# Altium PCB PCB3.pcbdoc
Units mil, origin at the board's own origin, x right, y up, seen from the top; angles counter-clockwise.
Board outline 4316.11 x 3910.52 mil, 4 copper layers (Top Layer, Inner1, Inner2, Bottom Layer), stack 5.512 mil thick; 63 components, 48 nets, 264 pads, 108 vias.
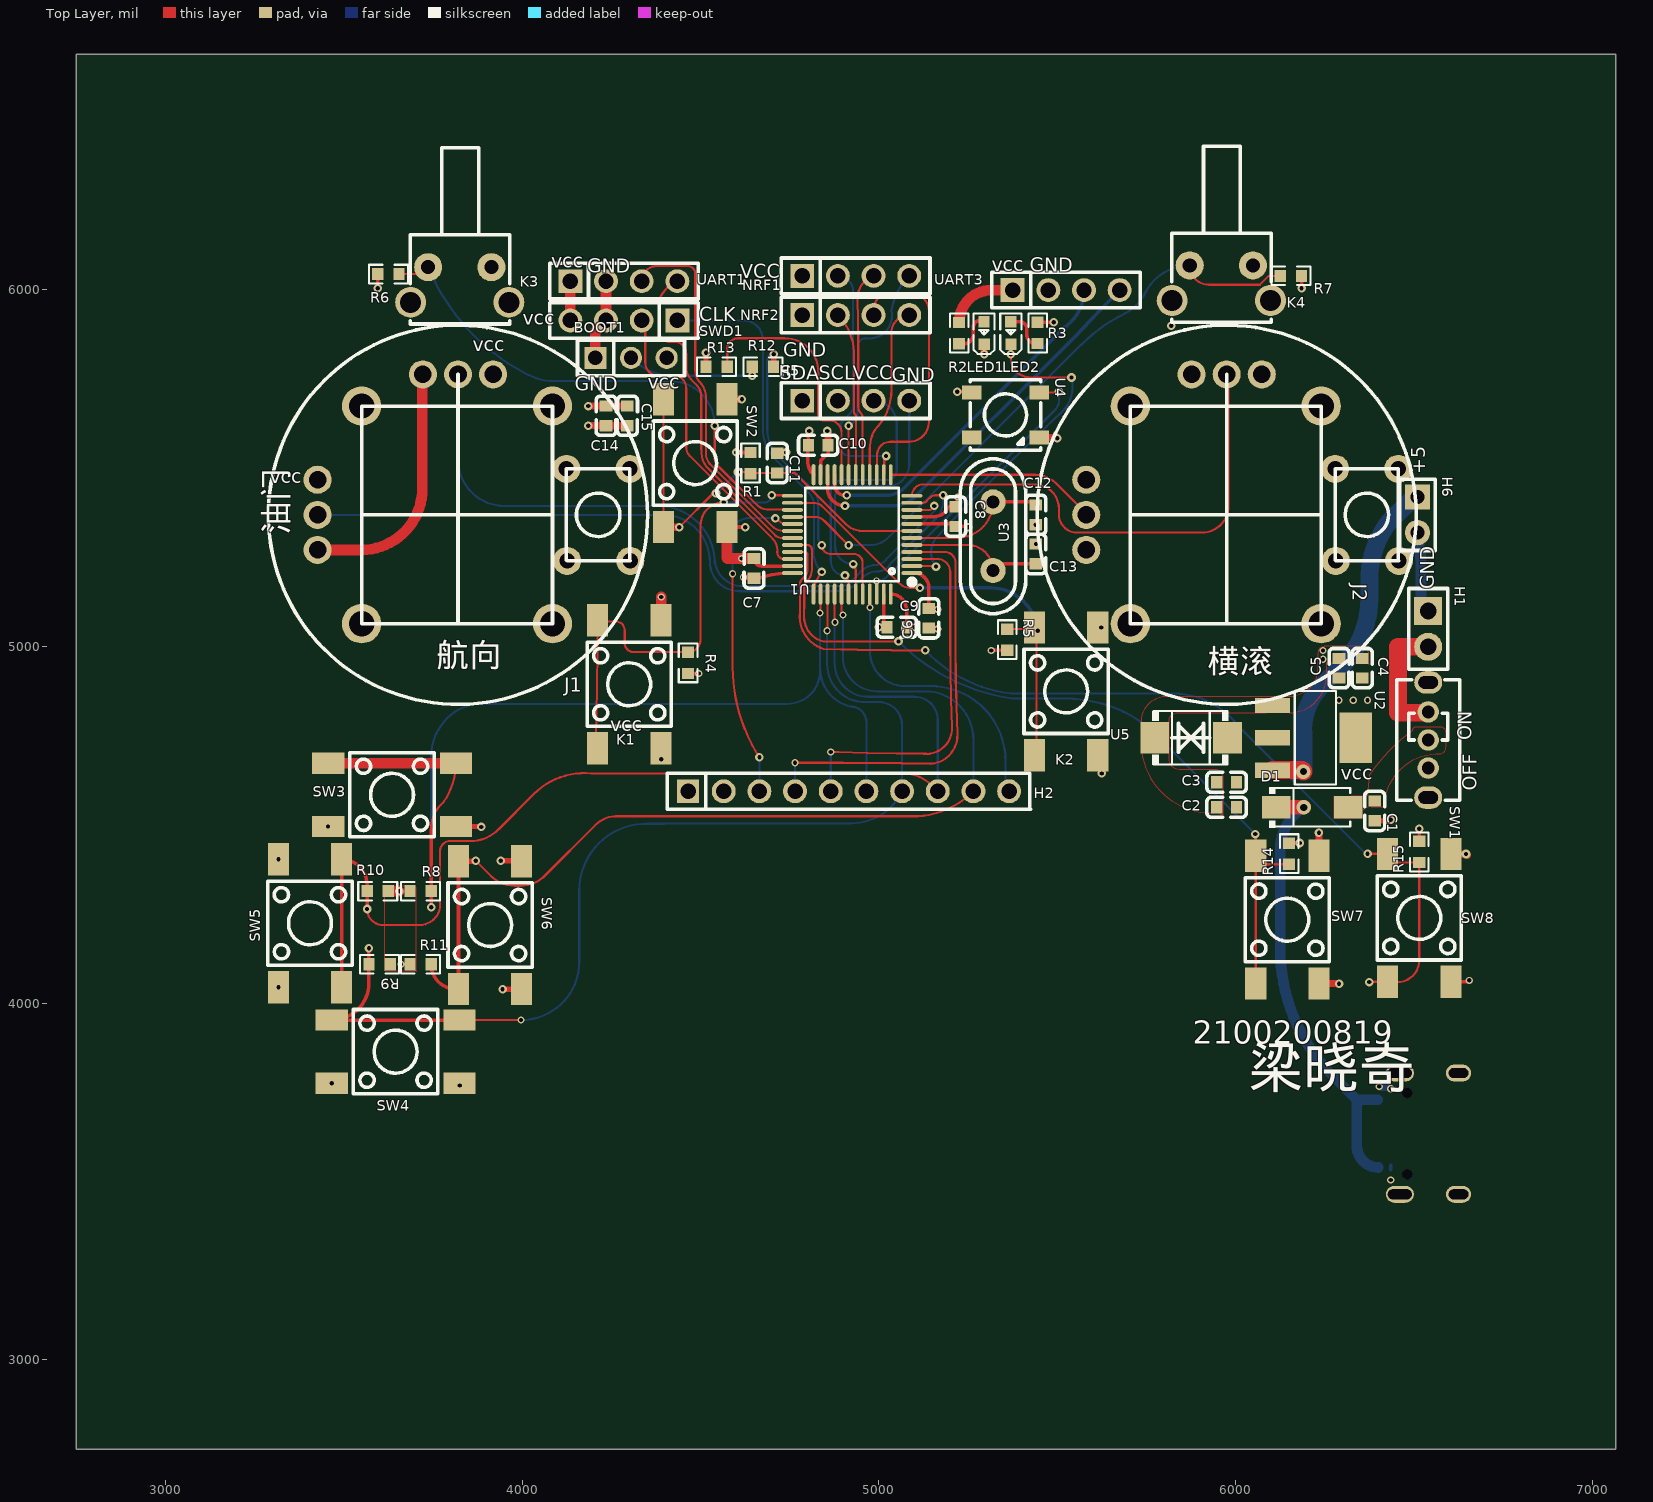
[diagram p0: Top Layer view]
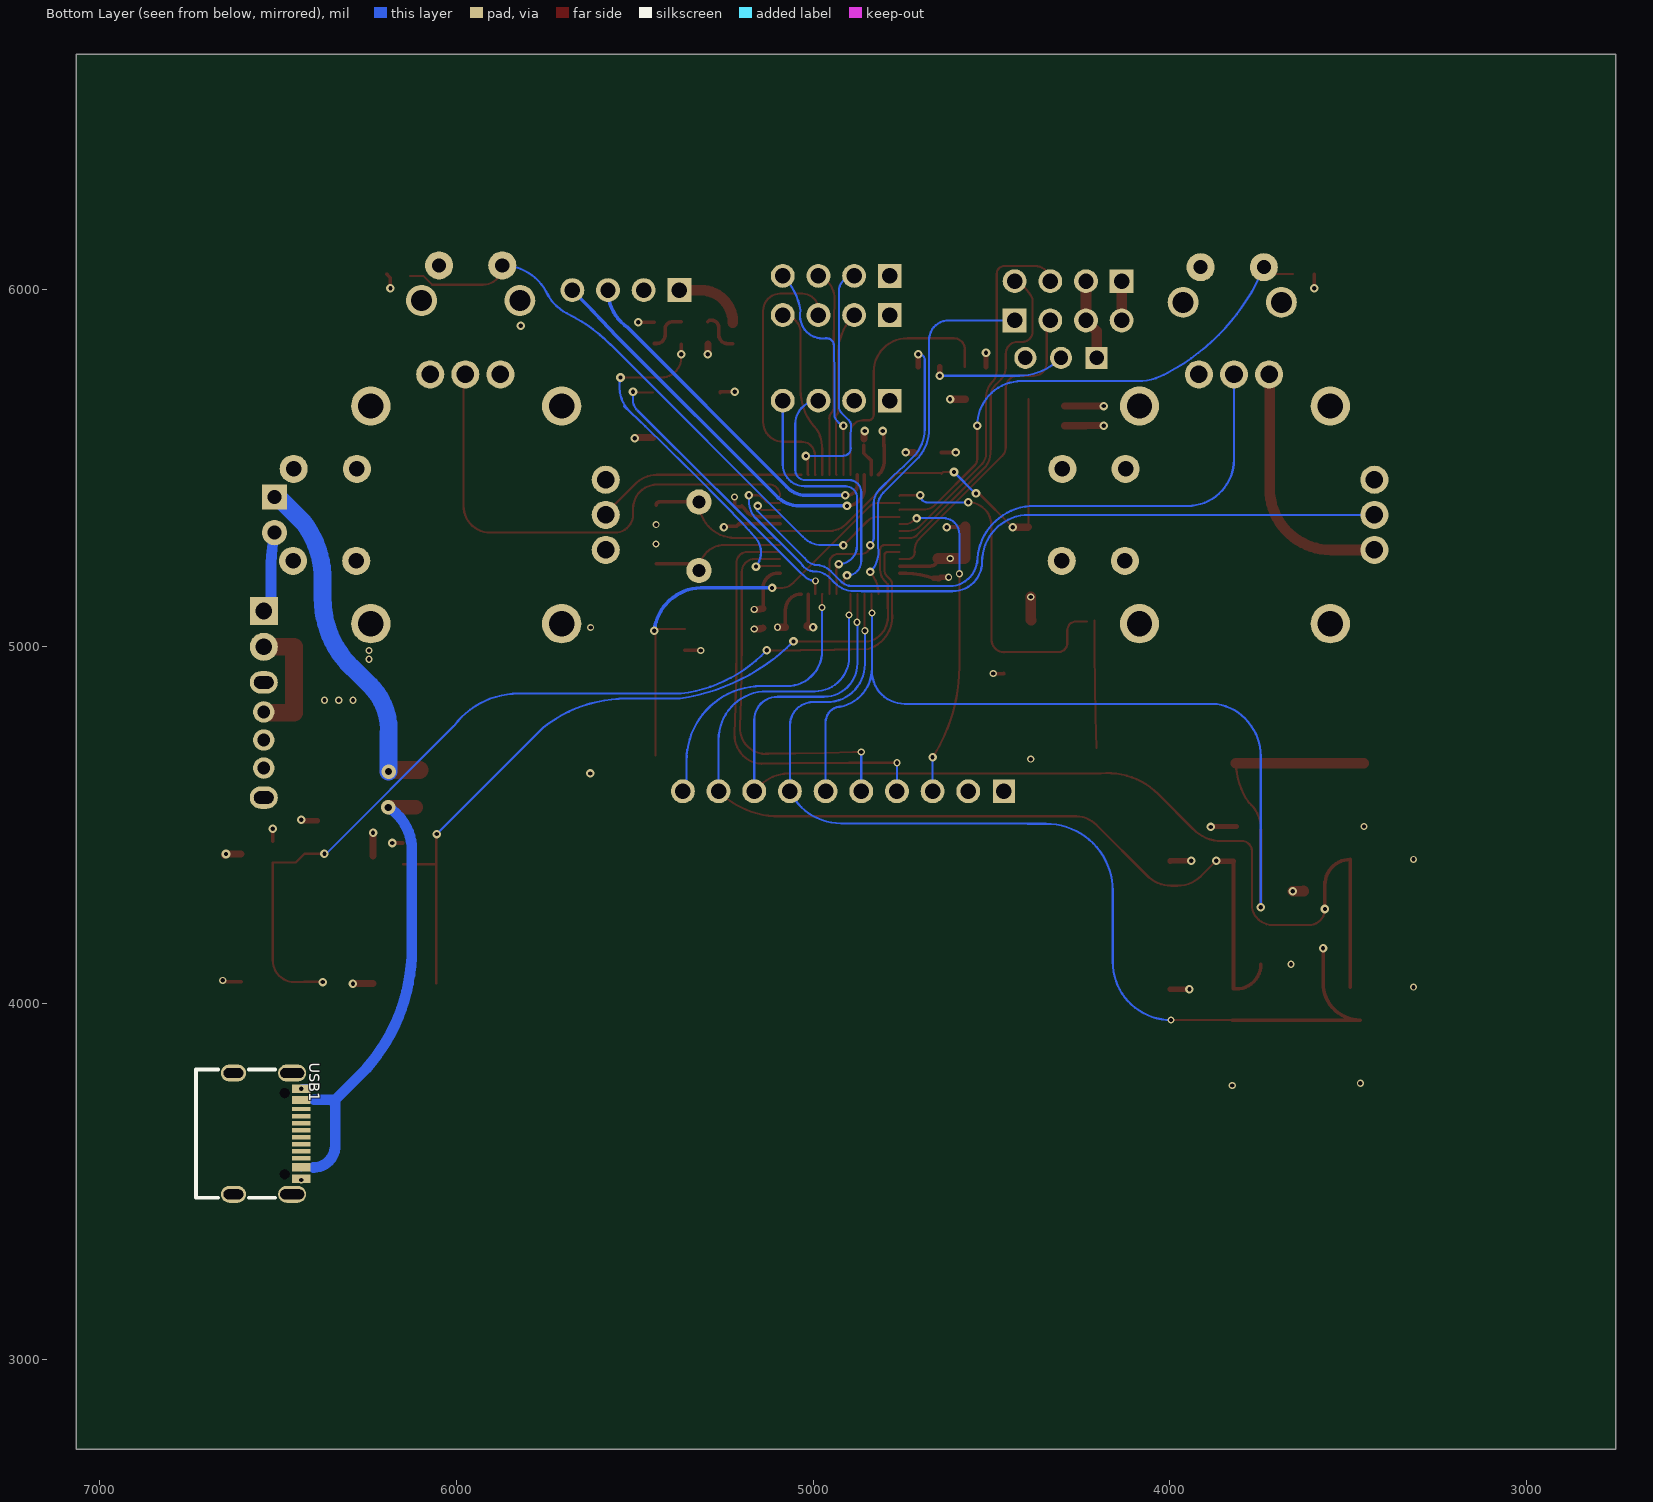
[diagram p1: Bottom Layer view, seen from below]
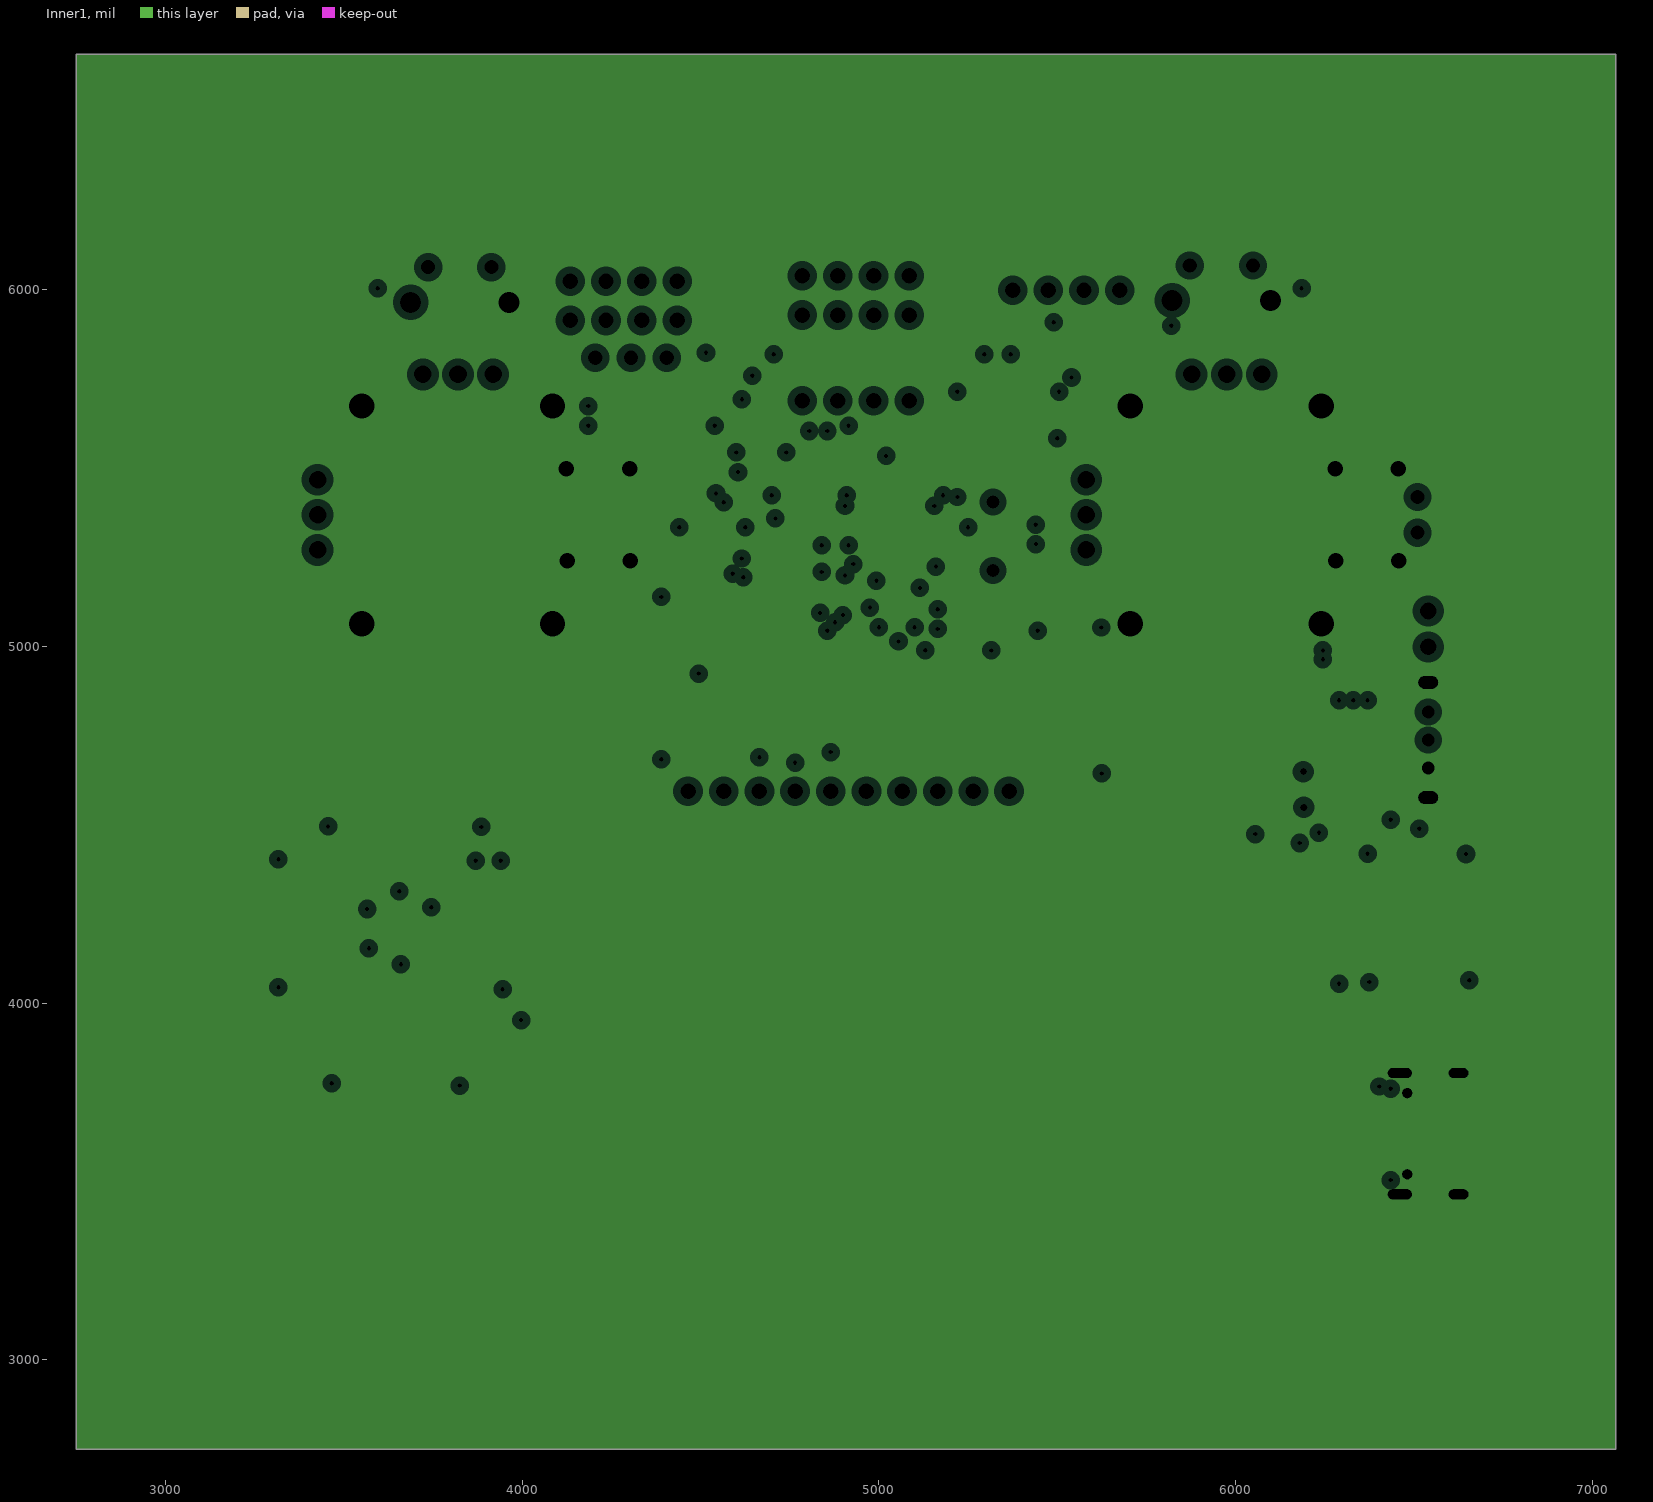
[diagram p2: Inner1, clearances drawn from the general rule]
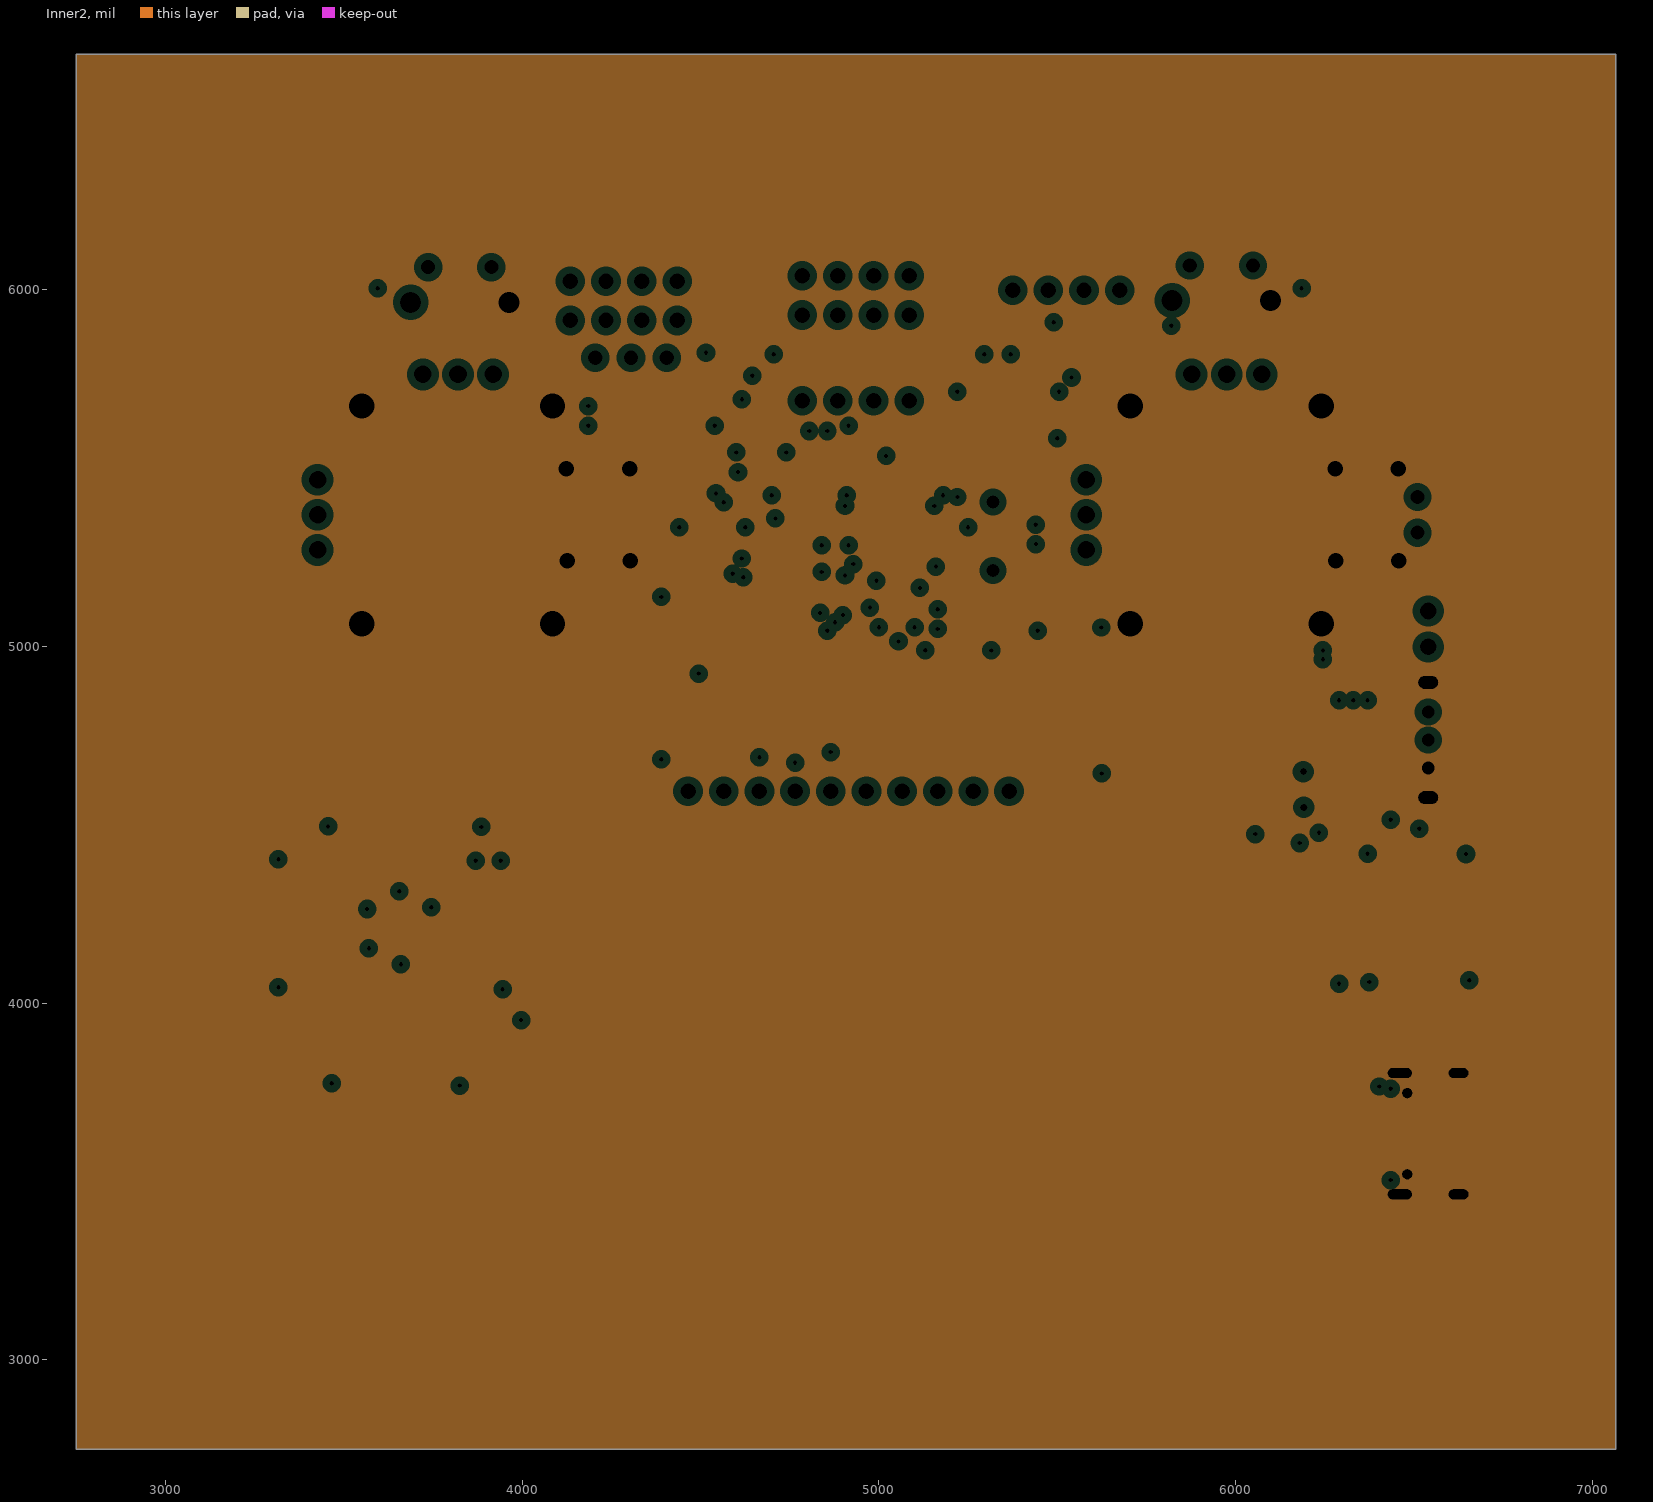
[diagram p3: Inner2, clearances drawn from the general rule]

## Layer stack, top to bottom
Top Layer: signal copper 1.378
Inner1: plane copper 1.378
Inner2: plane copper 1.378
Bottom Layer: signal copper 1.378

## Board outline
7066.11,2750 2750,2750 2750,6660.52 7066.11,6660.52

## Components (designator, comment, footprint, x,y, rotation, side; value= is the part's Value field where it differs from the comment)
BOOT1 "HDR-F_2.54_1x3P" HDR-TH_3P-P2.54-V-F 4305.29,5809.22 r0 top
C1 "100nF" C0603 6390.29,4539.22 r90 top
C2 "22uf" C0603 5975.29,4549.22 r0 top
C3 "0.1uf" C0603 5975.29,4619.22 r0 top
C4 "22uf" C0603 6355.29,4939.22 r270 top
C5 "0.1uf" C0603 6290.29,4939.22 r270 top
C6 "100nF" C0603 5140.29,5079.22 r90 top
C7 "100nF" C0603 4650.29,5219.22 r90 top
C8 "100nF" C0603 5215.29,5364.22 r270 top
C9 "100nF" C0603 5050.29,5054.22 r180 top
C10 "100nF" C0603 4830.29,5564.22 r0 top
C11 "100nF" C0603 4715.29,5514.22 r270 top
C12 "100nF" C0603 5440.29,5369.22 r270 top
C13 "100nF" C0603 5440.5,5259.83 r90 top
C14 "0.1UF" C0603 4235.29,5646.66 r270 top
C15 "10UF" C0603 4295.29,5646.66 r270 top
D1 "1N4007" SMA_L4.4-W2.8-LS5.4-RD 6215.29,4549.22 r0 top
H1 "HDR-F_2.54_1x2P" HDR-TH_2P-P2.54-V-F 6540.29,5049.22 r270 top
H2 "HDR-F_2.54_1x10P" HDR-TH_10P-P2.54-V-F 4915.29,4594.22 r0 top
H5 "HDR-F_2.54_1x4P" HDR-TH_4P-P2.54-V-F 4935.29,5689.22 r0 top
H6 "HDR-M_2.54_1x2P" HDR-TH_2P-P2.54-V-M-1 6510.29,5369.22 r270 top
J1 "_1" 摇杆带确认16*16 3990.29,5304.22 r180 top
J2 "_1" 摇杆带确认16*16 6145.29,5304.22 r180 top
K1 "Key_SMD_6x6x6.5" SW-SMD_4P-L6.0-W6.0-P4.50-LS9.0-2 4300.29,4894.22 r270 top
K2 "Key_SMD_6x6x6.5" SW-SMD_4P-L6.0-W6.0-P4.50-LS9.0-2 5525.29,4874.22 r270 top
K3 "按键开关6*6*8.5  带支架" KEY-TH_C61279 3825.29,6014.22 r180 top
K4 "按键开关6*6*8.5  带支架" KEY-TH_C61279 5960.29,6019.22 r180 top
LED1 "LED_0603-R" LED0603-RD_BLUE 5295.29,5879.22 r90 top
LED2 "LED_0603-R" LED0603-RD_BLUE 5370.29,5879.22 r90 top
NRF1 "HDR-F_2.54_1x4P" HDR-TH_4P-P2.54-V-F 4935.29,6039.22 r0 top
NRF2 "HDR-F_2.54_1x4P" HDR-TH_4P-P2.54-V-F 4935.29,5929.22 r0 top
R1 "10K" R0603 4640.29,5514.22 r270 top
R2 "10K" R0603 5225.29,5878.88 r270 top
R3 "10K" R0603 5445.29,5879.22 r90 top
R4 "10K" R0603 4465.29,4954.22 r270 top
R5 "10K" R0603 5360.29,5019.22 r270 top
R6 "10K" R0603 3625.29,6044.22 r180 top
R7 "10K" R0603 6155.29,6039.22 r0 top
R8 "10K" R0603 3715.29,4314.22 r180 top
R9 "10K" R0603 3600.29,4109.22 r0 top
R10 "10K" R0603 3595.29,4314.22 r0 top
R11 "10K" R0603 3715.29,4109.22 r180 top
R12 "10K" R0603 4675.29,5784.22 r0 top
R13 "10K" R0603 4545.29,5784.22 r0 top
R14 "10K" R0603 6150.29,4419.22 r90 top
R15 "10K" R0603 6515.29,4424.22 r90 top
SW1 "SS-12D02-G3" SW-TH_SS-12D02-G3 6540.29,4737.92 r270 top
SW2 "Key_SMD_6x6x6.5" SW-SMD_4P-L6.0-W6.0-P4.50-LS9.0-2 4485.29,5514.22 r270 top
SW3 "Key_SMD_6x6x6.5" SW-SMD_4P-L6.0-W6.0-P4.50-LS9.0-2 3635.29,4584.22 r180 top
SW4 "Key_SMD_6x6x6.5" SW-SMD_4P-L6.0-W6.0-P4.50-LS9.0-2 3645.29,3864.22 r180 top
SW5 "Key_SMD_6x6x6.5" SW-SMD_4P-L6.0-W6.0-P4.50-LS9.0-2 3405.29,4224.22 r90 top
SW6 "Key_SMD_6x6x6.5" SW-SMD_4P-L6.0-W6.0-P4.50-LS9.0-2 3910.29,4219.22 r270 top
SW7 "Key_SMD_6x6x6.5" SW-SMD_4P-L6.0-W6.0-P4.50-LS9.0-2 6145.29,4234.22 r270 top
SW8 "Key_SMD_6x6x6.5" SW-SMD_4P-L6.0-W6.0-P4.50-LS9.0-2 6515.29,4239.22 r270 top
SWD1 "HDR-F_2.54_1x4P" HDR-TH_4P-P2.54-V-F 4285.29,5914.22 r180 top
U1 "STM32F103C8T6" LQFP-48_L7.0-W7.0-P0.50-LS9.0-BL 4925.29,5314.22 r90 top
U2 "AMS1117-ADJRG" SOT-223-3_L6.4-W3.5-P2.30-LS7.0-BR 6220.29,4744.22 r180 top
U3 "8M" HC-49S_L11.0-W4.7-P4.88 5320.29,5309.22 r270 top
U4 "rgb-5050" LED-SMD_4P-L5.0-W5.0-BL_XL-5050RGBC 5355.29,5649.22 r270 top
U5 "SMB6.0TVS-SMB" SMB_L4.3-W3.6-LS5.4-BI 5875.29,4744.22 r180 top
UART1 "HDR-F_2.54_1x4P" HDR-TH_4P-P2.54-V-F 4285.29,6024.22 r0 top
UART3 "HDR-F_2.54_1x4P" HDR-TH_4P-P2.54-V-F 5525.29,5999.22 r0 top
USB1 "USB_TYPE-C-16P" USB-C-SMD_KH-TYPE-C-16P 6530.29,3634.22 r270 bottom

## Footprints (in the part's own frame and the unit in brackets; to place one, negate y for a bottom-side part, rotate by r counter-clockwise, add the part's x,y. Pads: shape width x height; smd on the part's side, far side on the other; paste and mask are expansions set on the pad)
C0603 [mm]
  rect 0.8x0.9 smd: 1(-0.7,0) 2(0.7,0)
  silkscreen extent -1.41,-0.71 1.39,0.72
HC-49S_L11.0-W4.7-P4.88 [mil]
  round 70.9 hole 35.4: 1(-96.1,0) 2(96.1,0)
  silkscreen extent -217,-92 217,92
HDR-TH_2P-P2.54-V-F [mil]
  rect 78.7x78.7 hole 47.2: 1(-50,0)
  round 78.7 hole 47.2: 2(50,0)
  silkscreen extent -113,-55 113,55
HDR-TH_2P-P2.54-V-M-1 [mm]
  rect 1.8x1.8 hole 1: 1(-1.27,0)
  round 1.8 hole 1: 2(1.27,0)
  silkscreen extent -2.54,-1.27 2.54,1.27
HDR-TH_3P-P2.54-V-F [mil]
  rect 62x62 hole 40.16: 1(-100,0)
  round 62 hole 40.16: 2(0,0) 3(100,0)
  silkscreen extent -150,-50 150,50
HDR-TH_4P-P2.54-V-F [mil]
  rect 66.9x66.9 hole 43.3: 1(-150,0)
  round 66.9 hole 43.3: 2(-50,0) 3(50,0) 4(150,0)
  silkscreen extent -208,-50 208,50
HDR-TH_10P-P2.54-V-F [mil]
  rect 62x66.9 hole 43.3: 1(-450,0)
  round 66.9 hole 43.3: 2(-350,0) 3(-250,0) 4(-150,0) 5(-50,0) 6(50,0) 7(150,0) 8(250,0) 9(350,0) 10(450,0)
  silkscreen extent -508,-50 510,50
KEY-TH_C61279 [mil]
  round 78.7 hole 39.4: 1(-88.6,-49.2) 2(88.6,-49.2)
  round 86.6 hole 59.1: 3(137.8,49.2) 4(-137.8,49.2)
  silkscreen extent -140,-384 138,110
LED0603-RD_BLUE [mil]
  rect 31.5x31.5 smd: 1(-31.5,-0.1) 2(31.5,0.1)
  silkscreen extent -59,-29 55,30
LED-SMD_4P-L5.0-W5.0-BL_XL-5050RGBC [mm]
  rect 1x1.4 smd: 1(-1.6,-2.4) 2(1.6,-2.4) 3(-1.6,2.4) 4(1.6,2.4)
  silkscreen extent -2.5,-2.5 2.5,2.5
LQFP-48_L7.0-W7.0-P0.50-LS9.0-BL [mm]
  oval 0.27x1.5 smd: 1(-2.75,-4.25) 2(-2.25,-4.25) 3(-1.75,-4.25) 4(-1.25,-4.25) 5(-0.75,-4.25) 6(-0.25,-4.25) 7(0.25,-4.25) 8(0.75,-4.25) 9(1.25,-4.25) 10(1.75,-4.25) 11(2.25,-4.25) 12(2.75,-4.25) 25(2.75,4.25) 26(2.25,4.25) 27(1.75,4.25) 28(1.25,4.25) 29(0.75,4.25) 30(0.25,4.25) 31(-0.25,4.25) 32(-0.75,4.25) 33(-1.25,4.25) 34(-1.75,4.25) 35(-2.25,4.25) 36(-2.75,4.25)
  oval 1.5x0.27 smd: 13(4.25,-2.75) 14(4.25,-2.25) 15(4.25,-1.75) 16(4.25,-1.25) 17(4.25,-0.75) 18(4.25,-0.25) 19(4.25,0.25) 20(4.25,0.75) 21(4.25,1.25) 22(4.25,1.75) 23(4.25,2.25) 24(4.25,2.75) 37(-4.25,2.75) 38(-4.25,2.25) 39(-4.25,1.75) 40(-4.25,1.25) 41(-4.25,0.75) 42(-4.25,0.25) 43(-4.25,-0.25) 44(-4.25,-0.75) 45(-4.25,-1.25) 46(-4.25,-1.75) 47(-4.25,-2.25) 48(-4.25,-2.75)
  silkscreen extent -3.59,-4.46 3.3,3.34
R0603 [mil]
  rect 31.75x34.02 smd: 1(-29.66,0) 2(29.66,0)
  silkscreen extent -55,-26 55,26
SMA_L4.4-W2.8-LS5.4-RD [mil]
  rect 80.57x63.78 smd: 1(-101,0) 2(101,0)
  silkscreen extent -121,-57 106,57
SMB_L4.3-W3.6-LS5.4-BI [mil]
  rect 80.6x88.2 smd: 1(-102,0) 2(102,0)
  silkscreen extent -105,-75 108,75
SOT-223-3_L6.4-W3.5-P2.30-LS7.0-BR [mil]
  rect 98.4x43.3 smd: 1(116.9,-90.5) 2(116.9,0) 3(116.9,90.6)
  rect 92.1x141.7 smd: 4(-116.9,0)
  silkscreen extent -62,-131 54,131
SW-SMD_4P-L6.0-W6.0-P4.50-LS9.0-2 [mm]
  rect 2.3x1.5 smd: 1(-4.55,2.25) 2(4.55,2.25) 3(-4.55,-2.25) 4(4.55,-2.25)
  silkscreen extent -3,-3 3,3
SW-TH_SS-12D02-G3 [mil]
  round 60 hole 36: 1(-78.7,0) 2(0,0) 3(78.7,0)
  oval 63x78.7 hole 35.4 slot 55.1 at 90 deg: 4(161.4,0) 5(-161.4,0)
  silkscreen extent -169,-89 169,89
USB-C-SMD_KH-TYPE-C-16P [mm]
  oval 1.2x2 hole 0.7 slot 1.7 at 90 deg: 1(-4.32,1.765) 2(4.32,1.765)
  oval 1.2x1.8 hole 0.7 slot 1.4 at 90 deg: 3(-4.32,-2.415) 4(4.32,-2.415)
  rect 0.3x1.3 smd: A1(-3.35,2.415) A4(-2.55,2.415) A5(-1.25,2.415) A6(-0.25,2.415) A7(0.25,2.415) A8(1.25,2.415) A9(2.55,2.415) A12(3.35,2.415) B1(3.05,2.415) B4(2.25,2.415) B5(1.75,2.415) B6(0.75,2.415) B7(-0.75,2.415) B8(-1.75,2.415) B9(-2.25,2.415) B12(-3.05,2.415)
  Multi-Layer board cut-out: -2.89,0.885 -3.042,0.92 -3.164,1.017 -3.231,1.157 -3.231,1.313 -3.164,1.453 -3.042,1.55 -2.89,1.585 -2.89,1.585 -2.738,1.55 -2.616,1.453 -2.549,1.313 -2.549,1.157 -2.616,1.017 -2.738,0.92 -2.89,0.885
  Multi-Layer board cut-out: 2.89,0.885 2.738,0.92 2.616,1.017 2.549,1.157 2.549,1.313 2.616,1.453 2.738,1.55 2.89,1.585 2.89,1.585 3.042,1.55 3.164,1.453 3.231,1.313 3.231,1.157 3.164,1.017 3.042,0.92 2.89,0.885
  silkscreen extent -4.57,-5.08 4.57,0.57
摇杆带确认16*16 [mm]
  round 2.8 hole 1.8: 0(-2.413,6.102) 0(-2.413,-9.398) 0(11.176,6.102) 0(11.176,-9.398)
  round 2 hole 1.25: 1(14.318,0.849) 2(14.318,-1.651) 3(14.318,-4.151) 4(6.818,-11.651) 5(4.318,-11.651) 6(1.818,-11.651)
  round 2 hole 1.1: J1(-7.95,1.626) J1(-7.904,-4.925) J2(-3.45,1.626) J2(-3.404,-4.925)
  silkscreen extent -9.18,-15.15 17.81,11.85

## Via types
v1: diameter 24.02, hole 12.01, Top Layer to Bottom Layer, 42 vias
v2: diameter 20, hole 11.81, Top Layer to Bottom Layer, 39 vias
v3: diameter 24, hole 12, Top Layer to Bottom Layer, 24 vias
v4: diameter 40, hole 20, Top Layer to Bottom Layer, 2 vias
v5: diameter 20, hole 11.8, Top Layer to Bottom Layer, 1 vias

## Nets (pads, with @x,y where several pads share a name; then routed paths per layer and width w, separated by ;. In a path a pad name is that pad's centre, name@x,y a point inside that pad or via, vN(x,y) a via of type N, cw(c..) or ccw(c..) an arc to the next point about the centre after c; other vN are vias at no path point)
$1N5516: LED1.2 R2.2 | length 117.3
  Top Layer w10: R2.2 5239.36,5849.22 ccw(c5239.36,5875.14) 5265.29,5875.14 5265.29,5895.85 cw(c5283.65,5895.85) 5283.65,5914.22 5291.69,5914.22 LED1.2
$1N5745: LED2.2 R3.1 | length 116.8
  Top Layer w10: LED2.2 5393.79,5910.72 cw(c5393.79,5889.22) 5415.29,5889.22 5415.29,5873.45 ccw(c5439.18,5873.45) 5439.18,5849.56 R3.1
$1N12540: BOOT1.2 R12.1 | length 379.7
  Top Layer w15: v1(4645.29,5759.22) 4645.29,5783.88 R12.1
  Bottom Layer w6: BOOT1.2 ccw(c4426.56,5930.49) 4435.46,5759.22 v1@4635.29,5759.22 ; v1@4636.75,5759.22 cw(c4641.75,5754.22) v1@4646.75,5759.22
+5V: C2.2 C3.2 D1.1 H6.1 U2.3 USB1.A4 USB1.A9 USB1.B4 USB1.B9 | length 2255
  Top Layer w40: D1.1 v4(6191.52,4549.22)
  Top Layer w50: U2.3 6185.89,4653.62 cw(c6185.89,4649.22) v4(6190.29,4649.22)
  Bottom Layer w10: USB1.A9 USB1.B4
  Bottom Layer w30: v4(6191.52,4549.22) ccw(c6265.8,4429.94) 6125.29,4429.94 6125.29,4153.73 ccw(c6634.32,4153.73) 6253.14,3816.37 6340.29,3729.22 6350.66,3729.22 ; 6399.17,3729.22 6350.66,3729.22 ; 6400.12,3539.22 cw(c6401.81,3600.71) 6340.29,3600.71 6340.29,3718.85 6350.66,3729.22
  Bottom Layer w50: v4(6190.29,4649.22) 6190.29,4757.96 cw(c6365.41,4766.39) 6241.44,4890.37 6282.5,4931.42 ccw(c6105.35,5135.1) 6375.29,5135.1 6375.29,5188.44 cw(c6639.16,5188.44) 6428.77,5347.69 6500.29,5419.22 H6.1
ADC1: J1.5 U1.10 | length 1959.7
  Top Layer w6: U1.10 5144.18,5383.11 ccw(c5138.18,5400.22) v3(5155.29,5394.22)
  Bottom Layer w6: J1.5 3820.29,5524.22 ccw(c3950.29,5524.22) 3950.29,5394.22 4380.29,5394.22 cw(c4380.29,5234.22) 4540.29,5234.22 ; 4539.72,5247.7 ccw(c4618.12,5247.7) 4618.12,5169.3 4865.2,5169.3 ccw(c4865.2,5878.83) 4901.29,5170.22 ; 4892.29,5169.82 ccw(c4892.29,5211.15) 4923.97,5184.6 4950.75,5211.38 cw(c4992.42,5169.71) 4989.65,5228.58 ccw(c4989.65,5267.82) 5023.38,5247.76 5155.83,5379.68 ccw(c5148.83,5386.7) v3(5155.29,5394.22)
ADC2: J1.2 U1.11 | length 2100.9
  Top Layer w6: U1.11 5123.26,5402.8 ccw(c5123.26,5416.9) 5134.65,5408.57 5143.25,5417.18 cw(c5160.4,5400.03) 5162.19,5424.22 v3(5180.29,5424.22)
  Bottom Layer w6: J1.2 4394.72,5369.22 cw(c4394.72,5237.27) 4526.67,5237.27 ccw(c4609.11,5237.27) 4609.11,5154.83 4843.48,5154.83 ccw(c4843.48,7014.07) 4884.79,5155.29 ccw(c4884.79,5231.49) 4940.16,5179.14 4953.92,5192.9 cw(c4995.77,5151.06) 4997.29,5210.22 ; 4995.01,5210.56 ccw(c4995.01,5255.48) 5033.75,5232.75 5163.17,5361.65 ccw(c5104.28,5409.7) 5180.29,5409.7 v3(5180.29,5424.22)
ADC3: J2.5 U1.12 | length 1415.3
  Top Layer w6: U1.12 cw(c5124.97,5422.49) 5118.6,5454.22 5437.69,5454.22 cw(c5437.69,5386.89) 5505.01,5386.89 ; 5504.92,5390.39 5504.92,5370.37 ccw(c5556.08,5370.37) 5556.08,5319.22 5905.29,5319.22 ccw(c5905.29,5394.22) 5980.29,5394.22 J2.5@5980.29,5746.6 ; J2.5@5975.3,5751.59 cw(c5975.3,5746.6) J2.5@5980.29,5746.6 ; J2.5 5980.29,5757.92 J2.5@5980.29,5746.6
ADC4: J2.2 U1.13 | length 593.1
  Top Layer w6: U1.13 5438.43,5481.53 cw(c5438.43,5397.96) 5495.41,5459.1 5581.59,5372.92 J2.2
BAT: H1.2 SW1.1 | length 356.4
  Top Layer w50: SW1.1 cw(c6537.89,4816.62) 6537.89,4814.22 6455.29,4814.22 6455.29,4999.22 H1.2
BOOT0: R12.2 U1.44 | length 874
  Top Layer w6: v3(4840.29,5284.22) ccw(c4865.29,5284.22) 4865.29,5259.22 4929.99,5259.22 4930.14,5259.37 cw(c4930.14,5234.69) 4954.81,5234.69 U1.44
  Top Layer w15: R12.2 4705.29,5784.56 v1@4705.29,5814.22 ; v1@4705.29,5814.22 v1(4705.29,5819.22) cw(c4702.66,5816.72) v1@4705.29,5814.22
  Bottom Layer w6: v1(4705.29,5819.22) 4702.29,5819.22 ccw(c4702.29,5804.22) 4687.29,5804.22 4687.29,5609.91 ccw(c4799.53,5609.91) 4712.75,5538.72 4746.27,5505.2 4775.38,5479.12 4814.3,5440.2 cw(c4775.62,5401.52) 4830.29,5403.57 4830.29,5302.73 ccw(c4866.29,5310.21) v3(4840.29,5284.22)
BOOT1: R13.2 U1.20 | length 708.5
  Top Layer w6: R13.2 4574.95,5833.88 cw(c4605.29,5833.88) 4605.29,5864.22 4736.13,5864.22 cw(c4736.13,5770.05) 4830.29,5770.05 4830.29,5649.22 ccw(c4845.29,5649.22) 4845.29,5634.22 4860.59,5634.22 cw(c4860.59,5599.05) 4895.75,5599.05 U1.20
GND: BOOT1.1 C1.1 C2.1 C3.1 C4.1 C5.1 C6.1 C7.2 C8.2 C9.2 C10.2 C11.1 C12.2 C13.2 C14.2 C15.2 H1.1 H2.2 H5.1 H6.2 J1.1 J1.4 J2.1 J2.4 K1.1 K1.2 K2.1 K2.2 K3.1 K3.3 K4.1 K4.3 LED1.1 NRF2.1 R13.1 SW2.1 SW2.2 SW3.1 SW3.2 SW4.1 SW4.2 SW5.1 SW5.2 SW6.1 SW6.2 SW7.1 SW7.2 SW8.1 SW8.2 SWD1.3 U1.8 U1.23 U1.35 U1.47 U2.1 U4.4 U5.2 UART1.2 UART3.2 USB1.A1 USB1.A12 USB1.B1 USB1.B12 | length 2808.3
  Top Layer w10: SW2.2@4573.96,5335.09 4614.42,5335.09 cw(c4618.71,5320.33) v1(4625.29,5334.22) ; C7.2 ccw(c4671.43,5246.78) 4671.43,5225.64 U1.35 ; U1.23 4836.71,5520.64 4857.85,5541.78 C10.2 ; U1.47 5013.87,5063.08 ccw(c5022.73,5063.08) C9.2 ; U1.8 5208.2,5343.74 C8.2 5247.85,5336.66 cw(c5247.85,5334.22) v1(5250.29,5334.22) ; SW8.2 6651.16,4060.09 v2(6655.29,4064.22)
  Top Layer w15: SW3.1 3883.87,4495.63 cw(c3883.87,4494.22) v1(3885.29,4494.22) ; v1(3940.29,4399.22) 3998,4399.22 cw(c3998,4398.35) SW6.1 ; v1(3945.29,4039.22) 3997.99,4039.22 ccw(c3997.99,4040.09) SW6.2 ; v1@4515.29,5824.22 cw(c4515.29,5823.88) v1(4515.63,5823.88) R13.1 ; C1.1 6432.73,4511.66 ccw(c6433.2,4513.74) v1(6435.29,4514.22)
  Top Layer w20: v1(4185.29,5619.22) 4235.17,5619.22 cw(c4235.17,5619.1) C14.2 C15.2 ; SW2.1 v1(4616.28,5693.35) ; C11.1 4717.73,5544.22 v1(4740.29,5544.22) ; v1(4855.29,5604.22) cw(c4793.04,5585.73) C10.2@4857.85,5581.66 ; v1(5000.29,5054.22) 5012.73,5054.22 C9.2@5017.73,5059.22 ; C6.1 ccw(c5160.4,5128.43) v2(5165.29,5049.22) ; v1@5295.29,5819.22 ccw(c5295.29,5819.32) v1(5295.39,5819.32) LED1.1 ; U4.4 5498.28,5586.22 cw(c5498.28,5584.22) v1(5500.29,5584.22) ; SW7.2 6286.16,4055.09 ccw(c6288.48,4055.86) v1(6290.29,4054.22) ; SW7.1 v1(6233.87,4477.8) cw(c6235.29,4477.8) v1@6235.29,4479.22 ; SW8.1 v1(6646.16,4418.35) cw(c6646.16,4414.22) v1@6650.29,4414.22
  Top Layer w30: J1.1 3548.63,5270.79 ccw(c3548.63,5442.45) 3720.29,5442.45 3720.29,5761.34 J1.4 ; BOOT1.1 4205.29,5884.22 SWD1.3 UART1.2 ; K1.1 4390.29,5074.76 v2(4390.29,5139.22) ; SW2.2 4573.87,5249.68 ccw(c4576.78,5249.68) 4576.78,5246.78 v2(4615.74,5246.78) C7.2 ; SW2.2@4573.86,5335.18 cw(c4573.86,5335.08) SW2.2@4573.96,5335.08
  Bottom Layer w20: v2(6402.98,3766.52) 6405.29,3764.22 6431.2,3764.22 v2(6435.21,3760.2)
  Bottom Layer w30: H6.2 cw(c5935.45,5211.53) 6520.29,5211.53 ; 6520.29,5239.22 6520.29,5211.53 ; H1.1 6520.29,5119.22 6520.29,5211.53
  other v1: 5625.29,4644.22 5820.29,5899.22
  other v2: 6435.29,3504.22 3825.29,3769.22 3466.16,3775.64 3316.7,4045.09 3316.71,4403.35 3316.71,4403.35 3456.16,4495.64 4390.29,4684.22 6245.29,4964.22 6245.29,4989.22 5623.87,5053.35 5623.87,5053.35 5440.5,5287.39 5440.29,5341.66
K5: H2.6 R8.1 SW3.3 SW3.4 U1.38 | length 3072.9
  Top Layer w6: 3744.95,4486.75 cw(c3837.77,4490.33) 3772.09,4556.01 3777.8,4561.73 ccw(c3627.65,4672.8) SW3.3 ; v2(4835.29,5094.22) 4836.7,5095.63 U1.38
  Top Layer w10: 3744.95,4486.75 R8.1 3744.95,4269.56 ccw(c3745.29,4269.56) v1(3745.29,4269.22)
  Top Layer w30: SW3.4 SW3.3
  Bottom Layer w6: v1(3745.29,4269.22) 3745.29,4692.72 cw(c3894,4692.72) 3868.42,4839.22 4743.66,4839.22 ccw(c4743.66,4930.85) 4835.29,4930.85 4835.29,4939.22 ; v2(4835.29,5094.22) 4835.29,4939.22 ; 4920.91,4831.95 cw(c4920.91,4787.57) 4965.29,4787.57 H2.6 ; 4935.29,4829.22 cw(c4945.79,4939.22) 4835.29,4939.22
K6: H2.7 R9.1 SW4.3 SW4.4 U1.39 | length 3032.1
  Top Layer w6: SW4.3 v2(3997.13,3952.8) ; v2(4855.29,5044.22) cw(c4857.02,5045.83) 4856.39,5048.12 U1.39
  Top Layer w10: v1@3570.29,4154.22 cw(c3570.29,4153.88) v1(3570.63,4153.88) R9.1 3570.63,4057.27 cw(c3466.16,4057.27) SW4.4 SW4.3
  Bottom Layer w6: v2(3997.13,3952.8) ccw(c3997.13,4115.96) 4160.29,4115.96 4160.29,4315.71 cw(c4347.57,4315.71) 4347.57,4502.99 4398.8,4502.99 ; v2(4855.29,5044.22) 4855.29,4950.22 ccw(c4961.29,4950.22) 4961.29,4844.22 5000.29,4844.22 cw(c5000.29,4779.44) 5065.07,4779.44 5065.07,4743.63 cw(c5065.07,4743.41) 5065.29,4743.41 5065.29,4736.76 cw(c-4935.3,4736.77) H2.7@5064.27,4594.24 ; H2.7@5065.29,4624.22 5060.29,4619.22 5060.29,4589.22 H2.7 cw(c4921.98,4663.31) 4921.98,4504.22 4400.02,4504.22 ; 4398.8,4502.99 ccw(c4398.8,4504.22) 4400.02,4504.22 ; 4398.8,4502.99 4400.02,4504.22
K7: H2.8 R10.1 SW5.3 SW5.4 U1.40 | length 3214.6
  Top Layer w6: v1(3565.29,4264.22) ccw(c3610.29,4264.22) 3610.29,4219.22 3712.37,4219.22 ccw(c3712.37,4277.14) 3770.29,4277.14 3770.29,4427.31 cw(c3797.72,4427.31) 3797.72,4454.75 3855.93,4454.75 ccw(c3855.93,4564.31) 3935.03,4488.5 4033.12,4586.59 cw(c4174.51,4445.2) 4193.85,4644.22 4978.61,4644.22 cw(c4978.62,-5355.04) 5070.29,4643.8 cw(c5069.25,4531.05) H2.8@5156.17,4602.87 ; U1.40 4876.07,5065 cw(c4877.59,5066.26) v2(4877.29,5068.22)
  Top Layer w10: SW5.3 SW5.4 cw(c3493.87,4331.59) 3565.63,4331.59 R10.1 v1@3565.63,4264.56
  Bottom Layer w6: v2@4876.29,5070.22 4876.29,4952.72 ccw(c4969.8,4952.72) 4969.8,4859.22 4969.99,4859.02 5100.1,4859.02 5100.29,4859.22 cw(c5100.29,4794.22) 5165.29,4794.22 H2.8
K8: H2.9 R11.1 SW6.3 SW6.4 U1.41 | length 2856.4
  Top Layer w6: v1(3870.29,4399.22) 3912.53,4356.98 ccw(c3979.55,4424) 3978.93,4329.22 3996.44,4329.22 ccw(c3996.44,4423.25) 4065.45,4359.38 4205.49,4499.42 cw(c4265.52,4439.4) 4262.13,4524.22 5109.12,4524.22 ccw(c5095.34,4764.17) H2.9 ; U1.41 4895.76,5091.75 v2(4899.29,5088.22)
  Top Layer w10: R11.1 ccw(c3814.08,4109.22) 3814.08,4040.09 SW6.4 SW6.3
  Top Layer w15: SW6.3 3869.42,4398.35 ccw(c3869.42,4399.22) v1(3870.29,4399.22)
  Bottom Layer w6: v2(4899.29,5088.22) 4899.29,4970.19 ccw(c4995.06,4970.19) 4995.06,4874.42 5130.09,4874.42 cw(c5130.09,4739.22) 5265.29,4739.22 H2.9
KA: R14.1 SW7.3 SW7.4 U1.32 | length 2262.9
  Top Layer w6: U1.32 4799.82,5284.68 cw(c4799.82,5272.22) 4812.29,5272.22 4812.29,5215.1 cw(c4766.53,5215.1) 4800.33,5184.26 4791,5174.93 cw(c-5209.68,5174.93) 4790.57,5082.7 ccw(c4860.74,5082.7) 4845.29,5014.25 ccw(c4872.42,15013.93) 4872.42,5014.22 v3(5055.29,5014.22) ; v1(6055.29,4474.22) cw(c6055.29,4472.8) 6056.7,4472.8 SW7.3 SW7.3@6056.7,4388 ; SW7.4 SW7.3@6056.7,4388 ; R14.1 6058.26,4389.56 SW7.3@6056.7,4388
  Bottom Layer w6: v3(5055.29,5014.22) ccw(c5456.12,5415.04) 5373.67,4854.22 5523.08,4854.22 cw(c5523.08,4478.21) 5756.55,4772.96 v1(6055.29,4474.22)
KB: R15.1 SW8.3 SW8.4 U1.33 | length 2743.2
  Top Layer w6: U1.33 4791.4,5265 cw(c4791.4,5256.12) 4800.29,5256.12 4800.29,5216.48 cw(c4769.62,5216.48) 4790.47,5193.99 4787.26,5190.78 ccw(c4798.34,5174.93) 4779,5174.93 ; 4779,5174.92 cw(c-5209.78,5174.94) 4778.78,5108.43 cw(c-5209.45,5174.9) 4778.57,5082.8 ccw(c4871.97,5082.81) 4845.4,4993.28 ccw(c5130.29,14989.14) v3(5130.29,4989.22) ; SW8.4 6381.16,4060.09 ccw(c6378.8,4055.79) v1(6375.29,4059.22) 6454.13,4059.22 ccw(c6454.13,4120.38) 6515.29,4120.38 R15.1 6450.49,4394.56 SW8.3 6425.83,4419.22 v1@6371.29,4419.22 ; v1@6371.29,4419.22 v1(6370.29,4419.22) cw(c6370.79,4419.68) v1@6371.29,4419.22
  Bottom Layer w6: v3(5130.29,4989.22) ccw(c5417.94,5261.4) 5370.7,4868.21 5826.15,4868.21 cw(c5826.15,4642.35) 6007.44,4777.07 6365.29,4419.22 v1(6370.29,4419.22)
KEY1: K1.3 K1.4 R4.1 U1.25 | length 1336.8
  Top Layer w6: K1.4@4205.29,4715.31 ccw(c-5788.3,5073.35) K1.3 ; K1.3@4233.19,5070.44 4263.07,5070.44 cw(c4263.07,5046.22) 4287.29,5046.22 cw(c4287.29,5045.86) 4287.64,5045.86 4287.64,5009.86 ccw(c4313.29,5009.86) 4313.29,4984.22 4464.95,4984.22 cw(c4464.95,4983.88) R4.1 ccw(c4464.6,5019.22) 4499.95,5019.22 ccw(c-5499.04,5101.4) 4500.29,5101.4 4500.29,5339.22 cw(c4565.29,5339.22) v3(4565.29,5404.22) ; v3(4700.29,5424.22) 4756.23,5424.22 U1.25
  Bottom Layer w6: v3(4565.29,5404.22) 4680.29,5404.22 ccw(c4680.29,5424.22) v3(4700.29,5424.22)
  other v3: 4700.29,5424.22
KEY2: K2.3 K2.4 R5.1 U1.26 | length 1291.2
  Top Layer w6: U1.26 4815.32,5402.79 cw(c4815.32,5362.9) 4841.57,5392.94 5055.55,5178.95 ccw(c5092.68,5216.08) 5100.86,5164.22 v3(5115.29,5164.22) ; R5.1 5440.63,5048.88 K2.3@5441.7,5047.8 ; K2.4@5441.7,4695.09 K2.3@5441.7,5047.8 ; K2.3@5441.7,5053.35 K2.3@5441.7,5047.8 ; v3(5445.29,5044.22) K2.3@5441.7,5047.8
  Bottom Layer w10: v3(5115.29,5164.22) 5315.29,5164.22 cw(c5312.92,5031.24) v3(5445.29,5044.22)
KEY3: K3.2 R6.1 U1.27 | length 1484.5
  Top Layer w6: R6.1 3717.49,6044.22 ccw(c3717.49,6063.42) K3.2 ; v3(4540.29,5619.22) 4540.29,5524.91 ccw(c4563.97,5524.91) 4546.54,5508.88 ; 4546.54,5508.87 4657.74,5397.67 ccw(c4691.26,5431.2) 4684.88,5384.22 4756.86,5384.22 U1.27
  Bottom Layer w6: K3.2 ccw(c4280.99,6288.87) 4005.29,5768.22 ; 4005.01,5768.19 ccw(c4089.99,5906.8) 4089.99,5744.22 4415.29,5744.22 cw(c4415.29,5619.22) v3(4540.29,5619.22)
KEY4: K4.2 R7.1 U1.28 | length 1764.6
  Top Layer w6: U1.28 4820.68,5363.42 cw(c4820.68,5326.18) 4847.75,5351.76 v3(4915.29,5284.22) ; K4.2 ccw(c5925.89,6068.42) 5925.89,6014.22 6068.33,6014.22 6093.33,6039.22 R7.1@6130.63,6039.22
  Bottom Layer w6: v3(4915.29,5284.22) 4974.82,5284.22 ccw(c4974.82,5357.95) 5028.95,5307.88 5560.85,5839.78 cw(c5659.06,5741.57) 5566.81,5845.4 cw(c5900.57,5511.64) 5690.29,5934.22 ccw(c5635.81,6043.69) 5745.29,5989.22 ; 5743.11,5983.49 cw(c5871.69,5928.61) K4.2
NRF_CE: NRF2.2 U1.18 | length 461.9
  Top Layer w6: NRF2.2 cw(c4776.37,5820.3) 4930.29,5826.23 4930.29,5660.29 ccw(c4940.68,5658.69) 4933.25,5651.26 cw(c4925.85,5643.87) 4936.29,5643.24 4936.29,5482.7 U1.18
NRF_CSN: NRF1.2 U1.14 | length 700.7
  Top Layer w6: U1.14 5015.29,5482.96 v3@5015.29,5524.22
  Bottom Layer w6: NRF1.2 cw(c4885.29,5996.77) 4927.74,5996.77 4927.74,5671.42 cw(c4904.43,5671.75) 4920.91,5655.27 4900.03,5634.39 ccw(c4914.82,5619.59) 4894.29,5615.61 cw(c3304.69,5559.22) 4895.29,5559.22 ccw(c4915.51,5555.35) 4915.29,5534.77 ccw(c5020.29,15533.94) v3(5020.29,5534.22)
NRF_IRQ: NRF1.4 U1.19 | length 643
  Top Layer w6: 4915.29,5539.22 cw(c4915.29,5539.06) 4915.44,5539.06 ; v3(4915.29,5619.22) 4915.44,5619.06 4915.44,5539.06 ; U1.19 4915.44,5539.06
  Bottom Layer w6: v3(4915.29,5619.22) ccw(c4897.61,5661.89) 4940.29,5644.22 4940.29,5656.69 cw(c14940.53,5656.68) 4942.05,5844.18 cw(c4962.63,5843.8) 4965.29,5864.22 ccw(c4973.49,5927.3) 5035.29,5942.4 cw(c5212.1,5912.41) NRF1.4
NRST: C11.2 R1.2 SW2.3 SW2.4 U1.7 | length 1186.7
  Top Layer w6: SW2.4 SW2.3 ; v1(4440.29,5334.22) 4535.29,5429.22 v3(4543.55,5429.22) ; v1(4605.29,5489.22) 4634.95,5489.22 R1.2@4639.95,5484.22 ; R1.2 cw(c4639.95,5484.56) R1.2@4639.95,5484.22 ; U1.7 5092.44,5324.22 4952.74,5324.22 cw(c4952.88,5386.06) 4909.15,5342.33 4773.67,5477.81 ccw(c4756.85,5466.26) 4756.85,5486.66 C11.2 4642.39,5486.66 ccw(c4642.39,5484.22) R1.2@4639.95,5484.22
  Top Layer w20: SW2.4 4397.57,5334.22 v1(4440.29,5334.22)
  Bottom Layer w6: v3(4543.55,5429.22) 4545.29,5429.22 v1(4605.29,5489.22)
OSCI: C13.1 U1.5 U3.2 | length 399.7
  Top Layer w6: U1.5 5248.72,5284.69 cw(c5248.72,5213.12) U3.2
  Top Layer w10: U3.2 cw(c5339.44,5213.12) 5339.44,5232.27 C13.1
OSCO: C12.1 U1.6 U3.1 | length 390.2
  Top Layer w6: U1.6@5112.6,5304.37 5219.34,5304.37 ccw(c5219.34,5405.32) U3.1
  Top Layer w10: U3.1 5431.75,5405.32 cw(c5431.75,5396.78) C12.1
PA8: H2.3 U1.29 | length 934.1
  Top Layer w6: v2(4590.29,5204.22) 4590.29,4942.64 ccw(c5058.42,4943.37) v3(4665.29,4689.22) ; v3(4710.29,5359.22) ccw(c4755.82,5404.75) 4735.2,5343.75 U1.29
  Bottom Layer w6: v2(4590.29,5204.22) 4590.29,5315.22 cw(c4635.29,5315.22) 4635.29,5360.22 4709.29,5360.22 cw(c4709.29,5359.22) v3(4710.29,5359.22) ; H2.3 v3(4665.29,4689.22)
PA13_SWDIO: SWD1.2 U1.34 | length 894.6
  Top Layer w6: SWD1.2 4345.29,5904.22 4345.29,5795.23 ccw(c4381.31,5795.23) 4381.31,5759.22 4425.31,5759.22 cw(c4425.31,5724.24) 4460.29,5724.24 4460.29,5557.19 ccw(c4491.62,5557.19) 4469.79,5534.71 4702.27,5302.23 cw(c4670.01,5269.97) 4715.29,5264.35 ccw(c4734.32,5264.35) 4734.32,5245.31 U1.34
PA14_SWCLK: SWD1.1 U1.37 | length 1047.6
  Top Layer w6: U1.37 cw(c4912.1,5146.9) v3(4840.29,5209.22)
  Bottom Layer w6: SWD1.1 4620.29,5914.22 cw(c4620.29,5859.22) 4675.29,5859.22 4675.29,5609.91 ccw(c4799.53,5609.91) 4703.86,5530.64 4803.55,5430.95 cw(c4766.91,5394.31) 4818.29,5401.06 4818.29,5278.68 ccw(c4896.22,5265.14) v3(4840.29,5209.22)
PB8: H2.10 U1.45 | length 806.6
  Top Layer w6: U1.45 4975.29,5146.11 v2(4975.29,5109.22)
  Bottom Layer w6: v2(4975.29,5109.22) 4975.29,4987.08 ccw(c5073.15,4987.08) 5073.15,4889.22 5145.29,4889.22 cw(c5145.29,4679.22) 5355.29,4679.22 5355.29,4604.22 ccw(c5365.29,4604.22) H2.10
PC14: H2.5 U1.3 | length 1077.1
  Top Layer w6: v2(4865.29,4704.22) ccw(c4888.41,6654.36) 4888.41,4704.08 ; 4884.87,4704.22 ccw(c5133.11,11075.76) 5133.11,4699.38 ; U1.3 5164.19,5245.32 cw(c5164.19,5209.22) 5200.29,5209.22 5200.29,5013.56 ; 5125.29,4699.22 ccw(c5132.97,4771.19) 5205.29,4774.22 cw(c10931.36,5013.56) 5200.29,5013.56 ; 5200.29,5005.68 5200.29,5013.56
  Bottom Layer w6: H2.5 v2(4865.29,4704.22)
PC15: H2.4 U1.4 | length 1204.3
  Top Layer w6: v2(4765.29,4674.22) 4899.47,4674.22 cw(c4899.47,-5325.45) 5145.22,4671.2 ccw(c5140.53,4750.89) 5220.29,4754.22 cw(c10961.4,4993.87) 5215.29,4993.87 ; U1.4 5184.5,5265.01 cw(c5184.5,5234.22) 5215.29,5234.22 5215.29,4993.88
  Bottom Layer w6: H2.4 v2(4765.29,4674.22)
RGBLED: U1.46 U4.3 | length 844.8
  Top Layer w6: v5(4993.29,5184.22) 4994.19,5183.32 U1.46 ; U4.3 5503.28,5712.21 ccw(c5503.28,5714.22) v1(5505.29,5714.22)
  Bottom Layer w6: v5(4993.29,5184.22) ccw(c4994.69,5224.48) 5021.29,5194.22 ccw(c4572.29,5705.22) 5053.29,5224.22 5491.37,5660.3 ccw(c5464.98,5690.77) 5505.29,5690.77 v1(5505.29,5714.22)
SCL: H5.3 U1.42 | length 736.9
  Top Layer w6: v3(4905.29,5199.22) cw(c4881.35,5175.28) U1.42@4915.16,5173.66
  Bottom Layer w6: v3(4905.29,5199.22) cw(c4905.29,5239.22) 4865.29,5239.22 4865.29,5433.24 cw(c4898.46,5433.24) 4898.46,5466.41 5022.48,5466.41 5022.9,5466.83 ccw(c5022.9,5494.22) 5050.29,5494.22 5050.29,5624.22 ccw(c4985.29,5624.22) H5.3
SDA: H5.4 U1.43 | length 741.6
  Top Layer w6: v3(4928.24,5231.27) cw(c4911.18,5214.21) 4935.29,5213.41 4935.29,5194.22 4935.12,5194.05 U1.43
  Bottom Layer w6: v3(4928.24,5231.27) cw(c4928.24,5282.22) 4877.29,5282.22 4877.29,5417.59 cw(c4908.91,5417.59) 4908.91,5449.22 5024.32,5449.22 ccw(c5024.32,5510.19) 5085.29,5510.19 H5.4
SPI1_SCK: NRF2.3 U1.15 | length 789
  Top Layer w6: NRF2.3 4985.29,5944.22 cw(c5030.29,5944.22) 5030.29,5989.22 5092.85,5989.22 cw(c5092.85,5941.78) 5140.29,5941.78 5140.29,5629.22 cw(c5085.29,5629.22) 5085.29,5574.22 5032.67,5574.22 ccw(c5032.67,5536.84) 4995.29,5536.84 4995.29,5482.64 cw(c4994.18,5482.64) U1.15
SPI2_MISO: NRF2.4 U1.16 | length 491.2
  Top Layer w6: U1.16 4974.5,5553.43 cw(c5080.93,5553.43) 4990.29,5609.22 ccw(c4881.64,5717.87) 5035.29,5719.22 5035.29,5879.22 cw(c5085.29,5879.22) NRF2.4
SPI3_MOSI: NRF1.3 U1.17 | length 576.7
  Top Layer w6: U1.17 4954.81,5635.84 ccw(c4929.55,5638.96) 4947.55,5656.95 cw(c4965.48,5671.66) 4942.29,5671.66 4942.29,5858.61 ccw(c1599.88,5858.61) 4940.29,5974.22 cw(c5006.43,5976.51) 4974.19,6034.3 cw(c5030.29,6024.22) NRF1.3@4976.21,6042.24
U1_RX: U1.31 UART1.4 | length 930.4
  Top Layer w6: UART1.4 ccw(c4470.64,5938.86) 4385.29,5974.22 4385.29,5882.05 ccw(c4413.13,5882.05) 4413.13,5854.22 4426.72,5854.22 cw(c4426.72,5820.65) 4460.29,5820.65 4460.29,5781.93 ccw(c4507.93,5781.93) 4472.93,5749.61 4488.45,5734.09 cw(c4454.88,5700.52) 4502.29,5702.91 4502.29,5553.82 ccw(c4586.12,5553.82) 4503.29,5540.91 4503.29,5540.7 ccw(c4557.87,5540.7) 4517.16,5504.34 4709.42,5312.05 ccw(c4727.97,5330.6) 4728.65,5304.38 U1.31
U1_TX: U1.30 UART1.3 | length 1037.8
  Top Layer w6: UART1.3 cw(c4377.74,6024.22) 4377.74,6066.67 4463.96,6066.67 cw(c4463.96,6045.34) 4485.29,6045.34 4485.29,5774.4 ccw(c4535.36,5774.4) 4495.8,5743.7 4498.25,5741.26 cw(c4456.93,5699.93) 4515.29,5702.91 4515.29,5540.7 ccw(c4557.87,5540.7) 4526.11,5512.34 4700.95,5337.49 ; 4701.01,5337.43 ccw(c4733.47,5369.9) 4730.99,5324.05 U1.30
U3_RX: U1.22 UART3.4 | length 1133.5
  Top Layer w10: U1.22 4856.38,5443.12 ccw(c4905.29,5443.12) v3(4905.29,5394.22)
  Bottom Layer w10: v3(4905.29,5394.22) 5038.32,5394.22 ccw(c5038.32,5483.7) 5103.99,5422.92 5551.23,5870.16 cw(c8879.75,2794.75) UART3.4
U3_TX: U1.21 UART3.3 | length 1004.2
  Top Layer w10: U1.21 4876.07,5452.84 ccw(c4904.69,5452.84) 4904.69,5424.22 v3(4910.29,5424.22)
  Bottom Layer w10: v3(4910.29,5424.22) 5020.29,5424.22 ccw(c5020.29,5498.43) 5078.61,5452.54 5520.38,5894.31 ccw(c5447.62,5999.22) UART3.3
USERLED1: LED2.1 U1.2 | length 1015.6
  Top Layer w6: U1.2 5127.96,5225.64 cw(c5138.4,5094.68) v3(5160.29,5224.22) ; v1(5370.29,5819.22) 5370.29,5809.22 ccw(c5425.29,5809.22) 5425.29,5754.22 v3(5540.29,5754.22)
  Top Layer w10: v1(5370.29,5819.22) ccw(c5370.29,5819.32) 5370.39,5819.32 LED2.1
  Bottom Layer w6: v3(5160.29,5224.22) cw(c5209.3,5263.61) 5161.29,5304.22 cw(c5961.47,4627.46) 5220.43,5368.5 cw(c5412.67,5203.7) 5233.62,5382.75 5350.55,5499.68 ; 5353.92,5502.82 cw(c11430.18,-573.43) 5530.29,5674.21 ; 5514.41,5659.18 ccw(c5444.27,5729.32) v3(5540.29,5754.22)
VBAT: C1.2 D1.2 SW1.2
VCC: BOOT1.3 C4.2 C5.2 C6.2 C7.1 C8.1 C9.1 C10.1 C14.1 C15.1 H2.1 H5.2 J1.3 J1.6 J2.3 J2.6 NRF1.1 R1.1 R2.1 R3.2 R4.2 R5.2 R6.2 R7.2 R8.2 R9.2 R10.2 R11.2 R14.2 R15.2 SWD1.4 U1.1 U1.9 U1.24 U1.36 U1.48 U2.2 U2.4 U4.1 U5.1 UART1.1 UART3.1 | length 1584.7
  Top Layer w10: v1@3595.29,6004.22 ccw(c3595.29,6004.56) v1(3595.63,6004.56) R6.2 ; R4.2 4465.63,4924.22 v2(4495.29,4924.22) ; v1@4610.29,5544.22 ccw(c4610.63,5544.22) 4610.63,5543.88 R1.1 ; C7.1@4662.68,5191.66 cw(c4757.97,4881.12) U1.36 ; v1(4805.29,5604.22) ccw(c4842.47,5589.83) 4802.73,5586.66 C10.1@4802.73,5566.59 ; U1.24 cw(c4857.45,5521.97) 4800.29,5523.45 C10.1@4800.29,5554.22 ; U1.48 cw(c5033.56,5102.61) 5077.85,5102.61 C9.1 ; U1.1 5098.56,5205.95 cw(c5098.56,5164.22) 5140.29,5164.22 C6.2@5140.29,5116.66 ; U1.9 5093.4,5364.22 5154.7,5364.22 ccw(c5154.7,5407.55) 5192.59,5386.52 C8.1@5197.85,5391.78 ; C8.1@5200.29,5394.22 C8.1@5197.85,5391.78 ; v2(5220.29,5419.22) 5220.29,5391.78 C8.1@5197.85,5391.78 ; v1(5220.29,5714.22) 5258.79,5714.22 cw(c5258.79,5712.21) U4.1 ; R2.1 5225.29,5954.22 ; v2(5315.29,4989.22) 5359.95,4989.22 R5.2 ; R3.2 5489.95,5908.88 ccw(c5489.95,5909.22) v1(5490.29,5909.22) ; R14.2 6150.63,4449.22 v1(6180.29,4449.22) ; v1(6185.29,6004.22) 6185.29,6033.88 6195.29,6043.88 ccw(c6194.95,6043.88) R7.2@6194.95,6044.22 ; R15.2 v1(6515.29,4488.76) ; C10.1@4800.29,5554.22 C10.1@4802.73,5566.59 ; C10.1@4800.29,5554.22 4800.29,5564.15 C10.1@4802.73,5566.59
  Top Layer w15: v2(4620.29,5194.22) 4642.85,5194.22 4647.85,5189.22 ccw(c4647.85,5191.66) C7.1 C7.1@4662.68,5191.66
  Top Layer w20: v1(4185.29,5674.22) ccw(c4187.79,5675.62) 4190.29,5674.22 C14.1 C15.1 ; C9.1 cw(c5077.84,-4943.55) v2(5100.29,5054.19) ; C6.2 ccw(c5160.78,5183.53) v2(5165.29,5104.22)
  Top Layer w30: R10.2 ccw(c3624.95,4314.56) 3625.29,4314.56 3625.63,4314.22 v1(3655.29,4314.22) ; SWD1.4 UART1.1 ; R2.1 cw(c5315.97,5908.54) 5315.97,5999.22 UART3.1 cw(c5375.29,5929.22) UART3.1@5381.28,5998.96
  other v1: 4600.29,5544.22
  other v2: 3660.29,4109.22 6290.29,4849.22 6330.29,4849.22 6370.29,4849.22
"": J1.0 J1.J1 J1.J2 J2.0 J2.J1 J2.J2 K3.4 K4.4 SW1.3 SW1.4 SW1.5 U4.2 USB1.1 USB1.2 USB1.3 USB1.4 USB1.A5 USB1.A6 USB1.A7 USB1.A8 USB1.B5 USB1.B6 USB1.B7 USB1.B8

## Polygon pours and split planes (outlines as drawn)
VBAT on Top Layer (solid, remove dead copper, pour order 0): 6275.29,4519.22 6355.29,4519.22 6355.29,4539.22 cw(c6376.57,4527.1) 6384.54,4550.25 6419.25,4550.25 cw(c6419.25,4549.22) 6420.29,4549.22 6420.29,4573.79 cw(c6420.7,4576.5) 6420.29,4579.22 cw(c6568.78,4547.52) 6575.29,4699.22 ccw(c6570.32,4718.57) 6590.29,4719.22 6590.29,4759.22 ccw(c6575.29,4759.22) 6575.29,4774.22 6505.71,4774.22 ccw(c6505.71,4763.69) 6495.19,4763.69 ccw(c6787.02,4362.61) 6375.29,4639.22 6369.6,4581.4 6275.42,4579.22 ccw(c6275.36,4578.72) 6275.39,4579.22 6275.29,4579.22
VBAT on Top Layer (solid, remove dead copper, pour order 1): 6275.42,4579.22 6275.29,4579.22 ccw(c6275.36,4578.72) 6275.39,4578.22 ccw(c6275.36,4578.72)
GND on Top Layer (solid, remove dead copper, pour order 4): 5965.29,4529.22 5965.29,4634.76 ccw(c5963.65,4634.76) 5963.65,4636.4 ccw(c5945.84,4636.4) 5945.84,4654.22 5845.29,4654.22 cw(c5845.29,4685.92) 5813.59,4685.92 5813.59,4791.08 cw(c5836.72,4791.08) 5836.72,4814.22 6082.89,4814.22 ccw(c6082.89,4834.72) 6103.39,4834.72 6129.79,4834.72 cw(c6129.79,4814.22) 6150.29,4814.22 ccw(c6150.29,4919.22) 6255.29,4919.22 6255.29,4954.22 6370.53,4954.22 cw(c6370.53,4950.86) 6373.89,4950.86 6373.89,4979.4 ccw(c6352.27,4979.4) 6352.27,5001.03 6252.1,5001.03 ccw(c6252.1,4979.22) 6230.29,4979.22 6230.29,4939.22 cw(c6150.29,4939.22) 6150.29,4859.22 5805.29,4859.22 ccw(c5805.29,4789.22) 5735.29,4789.22 5735.29,4730.55 ccw(c5932.15,4730.55) 5932.15,4533.69 ccw(c5932.15,4545.33) 5943.79,4545.33 5943.79,4549.22 5947.73,4549.22 5947.73,4546.78 ccw(c5965.29,4546.78)
VCC on Top Layer (solid, remove dead copper, pour order 5): 3625.29,4329.62 3697.29,4329.62 3701.71,4325.2 3701.71,4092.8 3705.29,4089.22 3618.12,4089.22 3614.86,4092.48 3614.86,4304.12 3624.95,4314.22 3624.95,4329.28

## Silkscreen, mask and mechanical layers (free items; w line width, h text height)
Top Silkscreen Layer:
  text "vcc" at 4081.96,6062.54 h38.94
  text "vcc" at 5316.96,6052.54 h38.94
  text "GND" at 5422.86,6050.21 h38.94
  text "GND" at 4181.96,6047.54 h38.94
  text "VCC" at 4611.96,6032.54 h38.94
  text "CLK" at 4496.96,5912.54 h38.94
  text "vcc" at 4001.96,5902.54 h38.94
  text "vcc" at 3861.96,5827.54 h38.94
  text "GND" at 4731.96,5812.54 h38.94
  text "SDA" at 4721.96,5747.54 h38.94
  text "SCL" at 4831.96,5747.54 h38.94
  text "VCC" at 4926.96,5747.72 h38.94
  text "GND" at 5036.96,5742.54 h38.94
  text "vcc" at 4351.96,5722.54 h38.94
  text "GND" at 4146.96,5717.54 h38.94
  text "+5" at 6531.97,5482.6 h38.94 r90
  text "vcc" at 3291.96,5457.54 h38.94
  text "油门" at 3342.75,5314.12 h67.97 r90
  text "GND" at 6556.97,5160.89 h38.94 r90
  text "航向" at 3759.65,4943.06 h67.97
  text "横滚" at 5920.2,4926.76 h67.97
  text "vcc" at 4246.96,4762.54 h38.94
  text "ON" at 6661.97,4737.6 h38.94 r90
  text "vcc" at 6294.72,4626.54 h38.94
  text "OFF" at 6676.97,4595.89 h38.94 r90
  text "2100200819" at 5879.8,3886.42 h64.9
  text "梁晓奇" at 6035.42,3765.12 h113.28
Mechanical 1:
  lines w10 net "": 4055.29,6099.22 ccw(c4151.54,6399.22) 4145.29,6084.22 4220.29,6084.22 ; 4900.29,6084.22 4095.29,6084.22 ; 4905.83,4464.22 5095.83,4464.22 cw(c5146.05,4100.25) 5510.83,4144.22 ccw(c7192.66,4247.65) 5945.83,3114.22 5960.83,3099.22 ccw(c6257.88,3494.31) 6625.83,3164.22 ccw(c5615.35,3812.89) 6815.83,3839.22 ccw(c-1596.76,3342.36) 6744.73,4541.52 6570.83,5679.22 ccw(c5979.99,5515.26) 6085.83,6119.22 ccw(c5959.65,5514.32) 5720.83,6084.22 4915.83,6084.22 ; 4910.29,4464.22 4720.29,4464.22 ccw(c4670.06,4100.25) 4305.29,4144.22 cw(c2623.45,4247.65) 3870.29,3114.22 3855.29,3099.22 cw(c3558.23,3494.31) 3190.29,3164.22 cw(c4200.76,3812.89) 3000.29,3839.22 cw(c11412.88,3342.36) 3071.38,4541.52 3245.29,5679.22 cw(c3836.12,5515.26) 3730.29,6119.22 cw(c3856.46,5514.32) 4095.29,6084.22 ; 4945.29,6084.22 4095.29,6084.22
